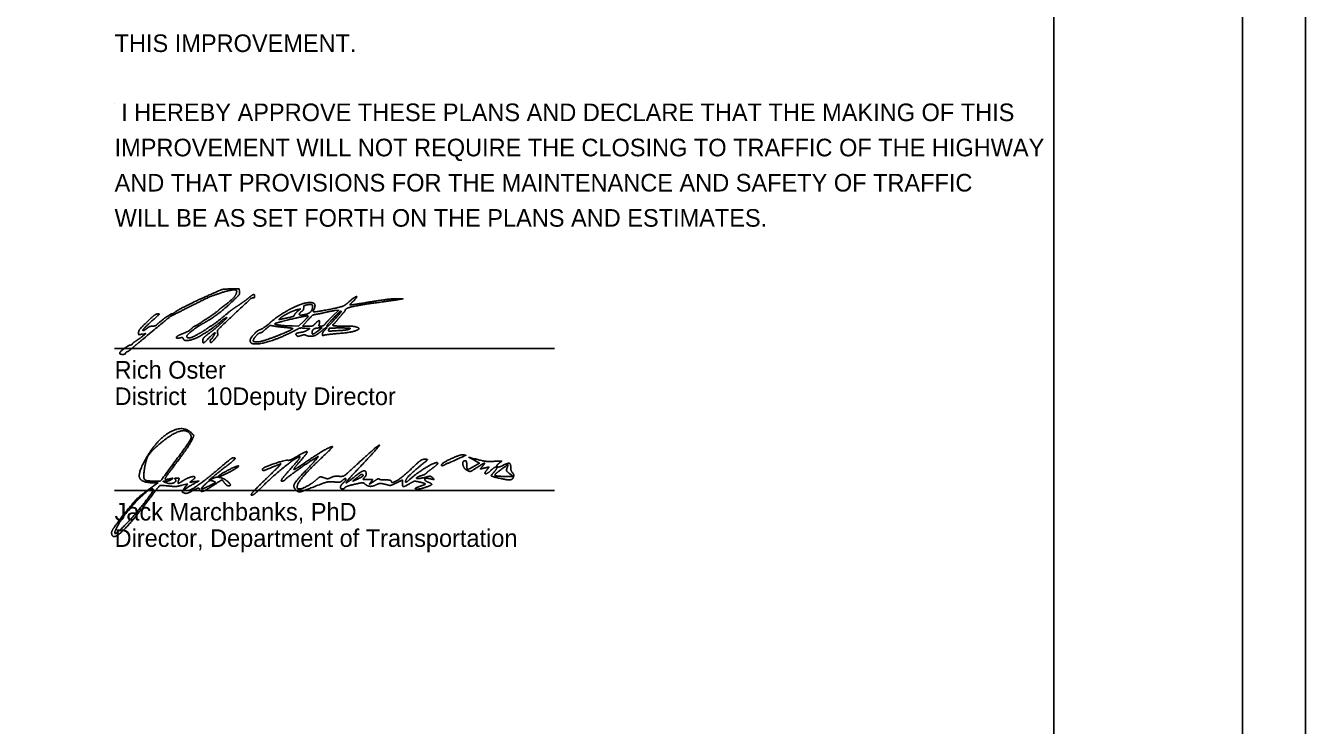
# Model space of a CAD drawing. Extents: x -20.2 to 34, y 0 to 22.
# Drawn here: x 23.82 to 34, y 5.57 to 11.14 of the extents above; entities that cross this region are included whole.
import ezdxf

# ---------------------------------------------------------------- set-up
doc = ezdxf.new("R2010")
doc.units = 0
for name, color, linetype in [('SH_Border', 7, 'Continuous'), ('SH_Cut_Line', 7, 'Continuous'), ('SH_Data', 7, 'Continuous'), ('SH_Text', 7, 'Continuous')]:
    doc.layers.add(name, color=color, linetype=linetype)

msp = doc.modelspace()

# ---------------------------------------------------------------- linework, layer by layer
at = {"layer": 'SH_Border'}
msp.add_line((32, 0.5), (32, 21.5), dxfattribs=at)
msp.add_lwpolyline([(1.5, 21.5), (33.5, 21.5), (33.5, 0.5), (1.5, 0.5)], close=True, dxfattribs=at)
at = {"layer": 'SH_Cut_Line'}
msp.add_lwpolyline([(0, 0), (34, 0), (34, 22), (0, 22)], close=True, dxfattribs=at)
at = {"layer": 'SH_Data'}
for p, q in [((24.528, 10.517), (24.528, 10.517)), ((24.528, 8.568), (28.028, 8.568)), ((24.528, 7.439), (28.028, 7.439))]:
    msp.add_line(p, q, dxfattribs=at)
at = {"layer": 'SH_Text'}
for p, q in [((24.569, 8.531), (24.569, 8.531)), ((24.99, 7.644), (24.99, 7.644)), ((27.129, 7.643), (27.129, 7.643)), ((25.356, 7.554), (25.356, 7.554)), ((26.504, 7.556), (26.504, 7.556)), ((27.582, 7.537), (27.582, 7.537)), ((25.311, 7.513), (25.311, 7.513)), ((25.727, 7.525), (25.727, 7.525))]:
    msp.add_line(p, q, dxfattribs=at)
for points in [[(25.521, 9.021), (25.518, 9.042), (25.458, 9.042)], [(26.782, 8.956), (26.823, 8.962), (26.785, 8.963)], [(25.983, 8.878), (26.006, 8.883), (25.981, 8.861)], [(26.278, 8.869), (26.311, 8.874), (26.267, 8.831)], [(26.032, 8.784), (25.992, 8.746), (25.939, 8.747)], [(26.064, 8.746), (26.023, 8.746), (26.063, 8.791)], [(24.747, 8.682), (24.776, 8.687), (24.753, 8.668)], [(26.041, 8.73), (26.08, 8.727), (26.059, 8.713)], [(26.152, 8.731), (26.177, 8.731), (26.147, 8.709)], [(27.393, 7.634), (27.43, 7.655), (27.389, 7.678)], [(26.453, 7.537), (26.423, 7.511), (26.464, 7.531)], [(27.642, 7.55), (27.698, 7.55), (27.669, 7.572)], [(24.843, 7.477), (24.873, 7.498), (24.835, 7.499)], [(25.085, 7.457), (25.107, 7.49), (25.065, 7.48)]]:
    msp.add_lwpolyline(points, dxfattribs=at)
for points in [[(25.233, 8.972), (25.153, 8.936), (25.017, 8.866), (25.004, 8.854)], [(25.151, 8.913), (25.263, 8.97), (25.288, 8.981), (25.361, 9.006)], [(25.458, 9.042), (25.396, 9.041), (25.369, 9.033), (25.233, 8.972)], [(25.361, 9.006), (25.425, 9.028), (25.499, 9.038), (25.499, 9.024)], [(25.375, 8.742), (25.597, 8.952), (25.619, 8.971), (25.632, 8.971)], [(25.499, 9.024), (25.499, 9), (25.454, 8.949), (25.395, 8.905)], [(25.46, 8.938), (25.514, 8.99), (25.523, 9.002), (25.521, 9.021)], [(25.593, 8.969), (25.576, 8.955), (25.539, 8.929), (25.511, 8.91)], [(25.642, 8.982), (25.642, 9), (25.624, 8.996), (25.593, 8.969)], [(25.632, 8.971), (25.638, 8.971), (25.642, 8.976), (25.642, 8.982)], [(26.429, 8.947), (26.465, 8.984), (26.436, 8.978), (26.393, 8.94)], [(26.785, 8.963), (26.741, 8.964), (26.657, 8.954), (26.525, 8.933)], [(24.742, 8.633), (24.966, 8.819), (24.976, 8.826), (25.151, 8.913)], [(25.355, 8.872), (25.34, 8.857), (25.173, 8.746), (25.166, 8.746)], [(25.237, 8.77), (25.291, 8.799), (25.406, 8.885), (25.46, 8.938)], [(25.395, 8.905), (25.38, 8.894), (25.362, 8.88), (25.355, 8.872)], [(25.511, 8.91), (25.482, 8.891), (25.448, 8.867), (25.436, 8.857)], [(25.94, 8.889), (25.898, 8.869), (25.789, 8.797), (25.763, 8.771)], [(25.844, 8.808), (25.859, 8.823), (25.954, 8.871), (25.983, 8.878)], [(26.084, 8.934), (26.057, 8.934), (25.995, 8.915), (25.94, 8.889)], [(25.981, 8.861), (25.968, 8.849), (25.957, 8.835), (25.957, 8.831)], [(26.086, 8.859), (26.07, 8.842), (25.989, 8.829), (25.998, 8.845)], [(25.998, 8.845), (26.002, 8.85), (26.011, 8.859), (26.018, 8.865)], [(26.018, 8.865), (26.026, 8.87), (26.032, 8.882), (26.032, 8.892)], [(26.032, 8.892), (26.032, 8.905), (26.037, 8.91), (26.055, 8.914)], [(26.055, 8.914), (26.068, 8.917), (26.083, 8.919), (26.089, 8.919)], [(26.114, 8.881), (26.127, 8.905), (26.111, 8.934), (26.084, 8.934)], [(26.089, 8.919), (26.104, 8.919), (26.102, 8.876), (26.086, 8.859)], [(26.11, 8.861), (26.107, 8.863), (26.11, 8.872), (26.114, 8.881)], [(26.343, 8.904), (26.316, 8.894), (26.114, 8.856), (26.11, 8.861)], [(26.204, 8.855), (26.227, 8.86), (26.26, 8.867), (26.278, 8.869)], [(26.329, 8.864), (26.332, 8.861), (26.308, 8.832), (26.256, 8.775)], [(26.304, 8.846), (26.316, 8.858), (26.327, 8.866), (26.329, 8.864)], [(26.309, 8.806), (26.328, 8.829), (26.347, 8.852), (26.352, 8.857)], [(26.393, 8.94), (26.374, 8.923), (26.351, 8.907), (26.343, 8.904)], [(26.352, 8.857), (26.358, 8.863), (26.362, 8.87), (26.362, 8.873)], [(26.362, 8.873), (26.362, 8.888), (26.484, 8.915), (26.655, 8.938)], [(26.525, 8.933), (26.405, 8.913), (26.396, 8.915), (26.429, 8.947)], [(26.655, 8.938), (26.702, 8.945), (26.759, 8.953), (26.782, 8.956)], [(24.783, 8.777), (24.737, 8.732), (24.719, 8.709), (24.719, 8.696)], [(24.752, 8.711), (24.749, 8.714), (24.796, 8.761), (24.852, 8.811)], [(24.862, 8.842), (24.854, 8.841), (24.819, 8.812), (24.783, 8.777)], [(24.867, 8.76), (24.86, 8.752), (24.843, 8.746), (24.831, 8.746)], [(24.852, 8.811), (24.88, 8.835), (24.883, 8.846), (24.862, 8.842)], [(24.985, 8.844), (24.976, 8.844), (24.886, 8.78), (24.867, 8.76)], [(25.004, 8.854), (24.997, 8.848), (24.989, 8.844), (24.985, 8.844)], [(25.102, 8.666), (25.102, 8.676), (25.198, 8.749), (25.237, 8.77)], [(25.155, 8.642), (25.192, 8.655), (25.319, 8.736), (25.364, 8.776)], [(25.436, 8.857), (25.391, 8.818), (25.298, 8.746), (25.293, 8.746)], [(25.38, 8.773), (25.366, 8.76), (25.348, 8.744), (25.341, 8.738)], [(25.364, 8.776), (25.379, 8.789), (25.397, 8.803), (25.405, 8.807)], [(25.405, 8.807), (25.425, 8.819), (25.413, 8.801), (25.38, 8.773)], [(25.763, 8.771), (25.748, 8.756), (25.689, 8.716), (25.681, 8.716)], [(25.802, 8.763), (25.8, 8.765), (25.825, 8.774), (25.857, 8.782)], [(25.939, 8.747), (25.884, 8.748), (25.809, 8.757), (25.802, 8.763)], [(25.852, 8.801), (25.835, 8.797), (25.834, 8.798), (25.844, 8.808)], [(25.914, 8.814), (25.89, 8.809), (25.862, 8.803), (25.852, 8.801)], [(25.857, 8.782), (25.954, 8.807), (26.063, 8.83), (26.067, 8.826)], [(25.957, 8.831), (25.957, 8.827), (25.937, 8.819), (25.914, 8.814)], [(26.067, 8.826), (26.069, 8.824), (26.053, 8.805), (26.032, 8.784)], [(26.063, 8.791), (26.095, 8.827), (26.107, 8.836), (26.132, 8.84)], [(26.123, 8.765), (26.108, 8.749), (26.098, 8.746), (26.064, 8.746)], [(26.156, 8.765), (26.162, 8.79), (26.146, 8.79), (26.123, 8.765)], [(26.132, 8.84), (26.149, 8.843), (26.182, 8.849), (26.204, 8.855)], [(26.17, 8.746), (26.154, 8.746), (26.152, 8.749), (26.156, 8.765)], [(26.206, 8.767), (26.196, 8.754), (26.182, 8.746), (26.17, 8.746)], [(26.267, 8.831), (26.243, 8.807), (26.215, 8.778), (26.206, 8.767)], [(26.22, 8.746), (26.212, 8.746), (26.233, 8.771), (26.304, 8.846)], [(26.256, 8.775), (26.241, 8.759), (26.225, 8.746), (26.22, 8.746)], [(26.264, 8.753), (26.264, 8.757), (26.267, 8.761), (26.27, 8.762)], [(26.27, 8.762), (26.273, 8.764), (26.291, 8.783), (26.309, 8.806)], [(24.753, 8.668), (24.741, 8.658), (24.716, 8.64), (24.699, 8.629)], [(24.719, 8.696), (24.719, 8.678), (24.721, 8.677), (24.747, 8.682)], [(24.782, 8.726), (24.768, 8.715), (24.755, 8.708), (24.752, 8.711)], [(24.831, 8.746), (24.818, 8.746), (24.797, 8.738), (24.782, 8.726)], [(25.051, 8.678), (25.02, 8.665), (25.018, 8.645), (25.048, 8.652)], [(25.048, 8.652), (25.064, 8.656), (25.071, 8.654), (25.074, 8.645)], [(25.141, 8.727), (25.122, 8.71), (25.107, 8.702), (25.051, 8.678)], [(25.18, 8.675), (25.143, 8.654), (25.102, 8.65), (25.102, 8.666)], [(25.166, 8.746), (25.163, 8.746), (25.152, 8.738), (25.141, 8.727)], [(25.28, 8.739), (25.265, 8.726), (25.217, 8.696), (25.18, 8.675)], [(25.287, 8.694), (25.247, 8.665), (25.229, 8.644), (25.229, 8.627)], [(25.279, 8.652), (25.318, 8.691), (25.332, 8.696), (25.313, 8.664)], [(25.293, 8.746), (25.291, 8.746), (25.285, 8.743), (25.28, 8.739)], [(25.341, 8.738), (25.334, 8.731), (25.31, 8.712), (25.287, 8.694)], [(25.313, 8.664), (25.306, 8.651), (25.298, 8.641), (25.295, 8.641)], [(25.327, 8.646), (25.344, 8.666), (25.35, 8.678), (25.347, 8.692)], [(25.347, 8.692), (25.344, 8.708), (25.35, 8.718), (25.375, 8.742)], [(25.681, 8.716), (25.67, 8.716), (25.613, 8.658), (25.608, 8.641)], [(25.635, 8.644), (25.645, 8.662), (25.679, 8.693), (25.691, 8.693)], [(25.652, 8.604), (25.702, 8.604), (25.861, 8.659), (25.959, 8.709)], [(25.691, 8.693), (25.695, 8.694), (25.706, 8.7), (25.713, 8.707)], [(25.713, 8.707), (25.758, 8.747), (25.769, 8.752), (25.797, 8.746)], [(25.944, 8.724), (25.935, 8.716), (25.833, 8.672), (25.769, 8.649)], [(25.797, 8.746), (25.813, 8.743), (25.854, 8.738), (25.888, 8.735)], [(25.888, 8.735), (25.922, 8.732), (25.948, 8.727), (25.944, 8.724)], [(25.959, 8.709), (25.993, 8.728), (26.009, 8.732), (26.041, 8.73)], [(26.008, 8.696), (25.977, 8.691), (25.966, 8.682), (25.978, 8.67)], [(25.978, 8.67), (25.983, 8.664), (25.994, 8.665), (26.012, 8.671)], [(26.059, 8.713), (26.047, 8.706), (26.024, 8.698), (26.008, 8.696)], [(26.012, 8.671), (26.027, 8.676), (26.043, 8.677), (26.048, 8.674)], [(26.048, 8.674), (26.062, 8.666), (26.109, 8.665), (26.126, 8.673)], [(26.099, 8.696), (26.099, 8.714), (26.126, 8.731), (26.152, 8.731)], [(26.147, 8.709), (26.116, 8.685), (26.099, 8.68), (26.099, 8.696)], [(26.126, 8.673), (26.134, 8.677), (26.155, 8.692), (26.173, 8.707)], [(26.173, 8.707), (26.205, 8.733), (26.225, 8.738), (26.197, 8.712)], [(26.197, 8.712), (26.189, 8.705), (26.182, 8.692), (26.182, 8.684)], [(26.182, 8.684), (26.182, 8.672), (26.185, 8.67), (26.199, 8.675)], [(26.199, 8.675), (26.208, 8.677), (26.251, 8.682), (26.294, 8.686)], [(26.305, 8.71), (26.241, 8.706), (26.227, 8.707), (26.23, 8.715)], [(26.23, 8.715), (26.233, 8.72), (26.234, 8.726), (26.234, 8.728)], [(26.234, 8.728), (26.234, 8.73), (26.274, 8.731), (26.322, 8.731)], [(26.345, 8.746), (26.301, 8.746), (26.264, 8.749), (26.264, 8.753)], [(26.294, 8.686), (26.406, 8.694), (26.494, 8.728), (26.443, 8.741)], [(26.397, 8.723), (26.389, 8.718), (26.347, 8.712), (26.305, 8.71)], [(26.322, 8.731), (26.389, 8.731), (26.407, 8.729), (26.397, 8.723)], [(26.443, 8.741), (26.433, 8.744), (26.389, 8.746), (26.345, 8.746)], [(24.659, 8.596), (24.645, 8.596), (24.569, 8.542), (24.569, 8.531)], [(24.627, 8.542), (24.635, 8.544), (24.649, 8.554), (24.659, 8.563)], [(24.659, 8.563), (24.67, 8.573), (24.707, 8.604), (24.742, 8.633)], [(24.667, 8.602), (24.667, 8.599), (24.663, 8.596), (24.659, 8.596)], [(24.699, 8.629), (24.681, 8.617), (24.667, 8.605), (24.667, 8.602)], [(25.074, 8.645), (25.08, 8.631), (25.119, 8.63), (25.155, 8.642)], [(25.229, 8.627), (25.229, 8.61), (25.247, 8.619), (25.279, 8.652)], [(25.289, 8.63), (25.289, 8.612), (25.301, 8.617), (25.327, 8.646)], [(25.295, 8.641), (25.292, 8.641), (25.289, 8.636), (25.289, 8.63)], [(25.608, 8.641), (25.605, 8.632), (25.607, 8.621), (25.612, 8.615)], [(25.612, 8.615), (25.617, 8.608), (25.634, 8.604), (25.652, 8.604)], [(25.636, 8.624), (25.629, 8.626), (25.629, 8.631), (25.635, 8.644)], [(25.769, 8.649), (25.712, 8.628), (25.653, 8.617), (25.636, 8.624)], [(24.569, 8.531), (24.569, 8.525), (24.578, 8.521), (24.592, 8.521)], [(24.592, 8.521), (24.604, 8.521), (24.614, 8.525), (24.614, 8.529)], [(24.614, 8.529), (24.614, 8.533), (24.62, 8.539), (24.627, 8.542)], [(24.779, 7.695), (24.865, 7.845), (25.073, 7.961), (25.139, 7.896)], [(25.13, 7.886), (25.104, 7.928), (24.978, 7.887), (24.883, 7.806)], [(24.99, 7.644), (25.112, 7.808), (25.144, 7.864), (25.13, 7.886)], [(25.139, 7.896), (25.158, 7.877), (25.158, 7.872), (25.139, 7.833)], [(24.883, 7.806), (24.816, 7.749), (24.777, 7.684), (24.766, 7.613)], [(25.139, 7.833), (25.128, 7.81), (25.077, 7.735), (25.024, 7.665)], [(25.974, 7.707), (26.052, 7.753), (26.065, 7.74), (26.005, 7.672)], [(26.033, 7.653), (26.113, 7.71), (26.244, 7.787), (26.26, 7.787)], [(26.26, 7.787), (26.265, 7.787), (26.224, 7.745), (26.168, 7.692)], [(26.487, 7.674), (26.562, 7.743), (26.628, 7.799), (26.634, 7.799)], [(26.634, 7.799), (26.639, 7.8), (26.587, 7.739), (26.518, 7.666)], [(24.835, 7.499), (24.737, 7.501), (24.714, 7.582), (24.779, 7.695)], [(24.844, 7.512), (24.891, 7.512), (24.895, 7.516), (24.99, 7.644)], [(25.024, 7.665), (24.972, 7.596), (24.929, 7.535), (24.929, 7.531)], [(25.369, 7.621), (25.419, 7.664), (25.465, 7.699), (25.47, 7.699)], [(25.47, 7.699), (25.495, 7.7), (25.472, 7.674), (25.386, 7.607)], [(26.002, 7.707), (25.992, 7.716), (25.782, 7.549), (25.704, 7.47)], [(25.705, 7.609), (25.705, 7.62), (25.892, 7.683), (25.908, 7.678)], [(25.727, 7.525), (25.798, 7.594), (25.854, 7.65), (25.85, 7.65)], [(25.85, 7.65), (25.847, 7.65), (25.818, 7.638), (25.786, 7.625)], [(26.142, 7.706), (26.093, 7.678), (25.905, 7.546), (25.891, 7.53)], [(25.908, 7.678), (25.914, 7.676), (25.943, 7.689), (25.974, 7.707)], [(25.924, 7.606), (25.97, 7.658), (26.005, 7.703), (26.002, 7.707)], [(26.005, 7.672), (25.977, 7.641), (25.954, 7.611), (25.954, 7.606)], [(25.954, 7.606), (25.954, 7.602), (25.99, 7.623), (26.033, 7.653)], [(26.168, 7.692), (26.069, 7.599), (25.979, 7.491), (25.979, 7.464)], [(26.077, 7.627), (26.123, 7.676), (26.152, 7.712), (26.142, 7.706)], [(26.312, 7.551), (26.345, 7.548), (26.369, 7.565), (26.487, 7.674)], [(26.518, 7.666), (26.388, 7.528), (26.356, 7.481), (26.439, 7.549)], [(26.967, 7.64), (26.893, 7.579), (26.842, 7.525), (26.842, 7.508)], [(26.876, 7.526), (26.93, 7.575), (27.077, 7.665), (27.094, 7.659)], [(26.895, 7.617), (26.94, 7.661), (26.977, 7.687), (26.995, 7.687)], [(26.995, 7.687), (27.019, 7.686), (27.016, 7.68), (26.967, 7.64)], [(27.094, 7.659), (27.102, 7.657), (27.087, 7.638), (27.06, 7.618)], [(27.129, 7.643), (27.129, 7.656), (27.282, 7.726), (27.301, 7.722)], [(27.201, 7.664), (27.138, 7.636), (27.129, 7.633), (27.129, 7.643)], [(27.301, 7.722), (27.322, 7.718), (27.323, 7.719), (27.201, 7.664)], [(27.33, 7.599), (27.304, 7.613), (27.293, 7.675), (27.317, 7.675)], [(27.317, 7.675), (27.324, 7.675), (27.329, 7.661), (27.329, 7.643)], [(27.329, 7.643), (27.329, 7.607), (27.344, 7.604), (27.393, 7.634)], [(27.389, 7.678), (27.346, 7.702), (27.345, 7.702), (27.448, 7.676)], [(27.453, 7.629), (27.477, 7.658), (27.461, 7.655), (27.405, 7.617)], [(27.448, 7.676), (27.469, 7.671), (27.514, 7.668), (27.548, 7.67)], [(27.548, 7.67), (27.603, 7.673), (27.608, 7.671), (27.588, 7.656)], [(27.588, 7.656), (27.559, 7.635), (27.582, 7.619), (27.616, 7.637)], [(27.65, 7.618), (27.66, 7.644), (27.651, 7.641), (27.589, 7.595)], [(27.616, 7.637), (27.656, 7.658), (27.679, 7.652), (27.679, 7.621)], [(24.766, 7.613), (24.755, 7.54), (24.776, 7.512), (24.844, 7.512)], [(24.964, 7.53), (24.989, 7.536), (24.993, 7.535), (24.979, 7.525)], [(25.009, 7.529), (25.004, 7.533), (25.01, 7.537), (25.022, 7.537)], [(25.022, 7.537), (25.037, 7.537), (25.042, 7.531), (25.037, 7.518)], [(25.074, 7.517), (25.102, 7.536), (25.167, 7.554), (25.167, 7.542)], [(25.108, 7.437), (25.131, 7.437), (25.257, 7.526), (25.369, 7.621)], [(25.167, 7.542), (25.167, 7.537), (25.157, 7.527), (25.145, 7.518)], [(25.386, 7.607), (25.293, 7.534), (25.271, 7.513), (25.315, 7.536)], [(25.315, 7.536), (25.328, 7.543), (25.351, 7.545), (25.368, 7.541)], [(25.359, 7.55), (25.354, 7.55), (25.353, 7.552), (25.356, 7.554)], [(25.356, 7.554), (25.376, 7.572), (25.508, 7.638), (25.513, 7.633)], [(25.513, 7.633), (25.519, 7.626), (25.377, 7.55), (25.359, 7.55)], [(25.368, 7.541), (25.404, 7.532), (25.463, 7.475), (25.436, 7.475)], [(25.786, 7.625), (25.723, 7.598), (25.704, 7.594), (25.705, 7.609)], [(25.858, 7.512), (25.848, 7.512), (25.877, 7.553), (25.924, 7.606)], [(25.97, 7.442), (25.945, 7.467), (25.973, 7.517), (26.077, 7.627)], [(26.137, 7.527), (26.157, 7.545), (26.17, 7.548), (26.194, 7.539)], [(26.194, 7.539), (26.214, 7.531), (26.233, 7.532), (26.249, 7.541)], [(26.249, 7.541), (26.262, 7.548), (26.291, 7.553), (26.312, 7.551)], [(26.367, 7.528), (26.367, 7.535), (26.357, 7.532), (26.344, 7.521)], [(26.439, 7.549), (26.487, 7.589), (26.529, 7.599), (26.529, 7.571)], [(26.504, 7.556), (26.504, 7.57), (26.48, 7.561), (26.453, 7.537)], [(26.464, 7.531), (26.486, 7.541), (26.504, 7.553), (26.504, 7.556)], [(26.514, 7.54), (26.503, 7.528), (26.509, 7.525), (26.541, 7.525)], [(26.529, 7.571), (26.529, 7.562), (26.523, 7.548), (26.514, 7.54)], [(26.729, 7.511), (26.729, 7.488), (26.825, 7.549), (26.895, 7.617)], [(26.97, 7.557), (26.921, 7.541), (26.94, 7.528), (26.992, 7.541)], [(27.004, 7.573), (27.001, 7.569), (26.986, 7.562), (26.97, 7.557)], [(26.992, 7.541), (27.03, 7.552), (27.045, 7.551), (27.058, 7.539)], [(27.039, 7.531), (27.002, 7.54), (26.989, 7.517), (27.023, 7.504)], [(27.06, 7.618), (27.033, 7.598), (27.008, 7.578), (27.004, 7.573)], [(27.058, 7.539), (27.07, 7.526), (27.067, 7.524), (27.039, 7.531)], [(27.405, 7.617), (27.365, 7.591), (27.352, 7.588), (27.33, 7.599)], [(27.472, 7.617), (27.439, 7.609), (27.437, 7.61), (27.453, 7.629)], [(27.492, 7.606), (27.507, 7.624), (27.505, 7.625), (27.472, 7.617)], [(27.521, 7.598), (27.489, 7.568), (27.466, 7.575), (27.492, 7.606)], [(27.546, 7.585), (27.577, 7.619), (27.555, 7.63), (27.521, 7.598)], [(27.582, 7.537), (27.527, 7.55), (27.522, 7.558), (27.546, 7.585)], [(27.589, 7.595), (27.546, 7.564), (27.563, 7.55), (27.642, 7.55)], [(27.7, 7.544), (27.692, 7.523), (27.651, 7.521), (27.582, 7.537)], [(27.669, 7.572), (27.649, 7.588), (27.643, 7.601), (27.65, 7.618)], [(27.679, 7.621), (27.679, 7.605), (27.686, 7.586), (27.694, 7.578)], [(27.694, 7.578), (27.701, 7.57), (27.704, 7.555), (27.7, 7.544)], [(24.835, 7.448), (24.814, 7.469), (24.596, 7.243), (24.55, 7.153)], [(24.592, 7.235), (24.669, 7.335), (24.749, 7.413), (24.843, 7.477)], [(24.62, 7.172), (24.687, 7.241), (24.843, 7.44), (24.835, 7.448)], [(24.924, 7.477), (24.89, 7.481), (24.879, 7.47), (24.802, 7.368)], [(24.936, 7.512), (24.913, 7.511), (24.914, 7.509), (24.94, 7.499)], [(25.065, 7.48), (25.025, 7.47), (25.002, 7.469), (24.924, 7.477)], [(24.929, 7.531), (24.929, 7.526), (24.945, 7.526), (24.964, 7.53)], [(24.979, 7.525), (24.969, 7.518), (24.949, 7.512), (24.936, 7.512)], [(24.94, 7.499), (24.97, 7.487), (25.026, 7.511), (25.009, 7.529)], [(25.037, 7.518), (25.029, 7.495), (25.041, 7.494), (25.074, 7.517)], [(25.084, 7.417), (25.066, 7.424), (25.066, 7.428), (25.085, 7.457)], [(25.151, 7.437), (25.125, 7.422), (25.095, 7.413), (25.084, 7.417)], [(25.152, 7.488), (25.101, 7.46), (25.081, 7.437), (25.108, 7.437)], [(25.145, 7.518), (25.126, 7.504), (25.128, 7.503), (25.161, 7.508)], [(25.202, 7.451), (25.199, 7.459), (25.18, 7.454), (25.151, 7.437)], [(25.161, 7.508), (25.198, 7.513), (25.198, 7.513), (25.152, 7.488)], [(25.316, 7.481), (25.248, 7.436), (25.21, 7.426), (25.202, 7.451)], [(25.258, 7.496), (25.213, 7.456), (25.225, 7.447), (25.283, 7.476)], [(25.311, 7.513), (25.293, 7.519), (25.277, 7.514), (25.258, 7.496)], [(25.283, 7.476), (25.329, 7.5), (25.333, 7.505), (25.311, 7.513)], [(25.401, 7.499), (25.384, 7.523), (25.382, 7.523), (25.316, 7.481)], [(25.436, 7.475), (25.426, 7.475), (25.411, 7.486), (25.401, 7.499)], [(25.617, 7.4), (25.607, 7.401), (25.656, 7.457), (25.727, 7.525)], [(25.704, 7.47), (25.667, 7.431), (25.627, 7.4), (25.617, 7.4)], [(25.891, 7.53), (25.883, 7.52), (25.868, 7.512), (25.858, 7.512)], [(26.169, 7.489), (26.023, 7.431), (25.988, 7.423), (25.97, 7.442)], [(25.979, 7.464), (25.979, 7.456), (25.988, 7.45), (25.998, 7.45)], [(25.998, 7.45), (26.019, 7.45), (26.101, 7.495), (26.137, 7.527)], [(26.275, 7.506), (26.246, 7.51), (26.206, 7.503), (26.169, 7.489)], [(26.344, 7.521), (26.329, 7.506), (26.307, 7.502), (26.275, 7.506)], [(26.341, 7.45), (26.323, 7.45), (26.327, 7.482), (26.348, 7.5)], [(26.359, 7.46), (26.356, 7.454), (26.348, 7.45), (26.341, 7.45)], [(26.348, 7.5), (26.359, 7.508), (26.367, 7.521), (26.367, 7.528)], [(26.436, 7.487), (26.397, 7.478), (26.363, 7.466), (26.359, 7.46)], [(26.52, 7.489), (26.509, 7.5), (26.489, 7.5), (26.436, 7.487)], [(26.616, 7.487), (26.585, 7.47), (26.538, 7.472), (26.52, 7.489)], [(26.541, 7.525), (26.579, 7.525), (26.581, 7.523), (26.565, 7.503)], [(26.565, 7.503), (26.553, 7.488), (26.56, 7.49), (26.587, 7.509)], [(26.587, 7.509), (26.609, 7.524), (26.629, 7.533), (26.633, 7.529)], [(26.681, 7.487), (26.654, 7.494), (26.631, 7.494), (26.616, 7.487)], [(26.633, 7.529), (26.637, 7.525), (26.66, 7.522), (26.685, 7.522)], [(26.77, 7.498), (26.732, 7.48), (26.714, 7.477), (26.681, 7.487)], [(26.685, 7.522), (26.709, 7.522), (26.729, 7.517), (26.729, 7.511)], [(26.817, 7.498), (26.817, 7.521), (26.816, 7.521), (26.77, 7.498)], [(26.879, 7.495), (26.834, 7.468), (26.817, 7.469), (26.817, 7.498)], [(26.842, 7.508), (26.842, 7.501), (26.857, 7.509), (26.876, 7.526)], [(26.962, 7.503), (26.923, 7.513), (26.906, 7.511), (26.879, 7.495)], [(26.998, 7.462), (26.952, 7.447), (26.904, 7.452), (26.948, 7.468)], [(26.948, 7.468), (26.962, 7.473), (26.982, 7.48), (26.992, 7.484)], [(26.992, 7.484), (27.003, 7.488), (26.992, 7.496), (26.962, 7.503)], [(27.023, 7.504), (27.054, 7.492), (27.045, 7.478), (26.998, 7.462)], [(24.802, 7.368), (24.65, 7.166), (24.504, 7.038), (24.504, 7.105)], [(24.504, 7.105), (24.504, 7.114), (24.544, 7.173), (24.592, 7.235)], [(24.55, 7.153), (24.518, 7.092), (24.55, 7.1), (24.62, 7.172)]]:
    msp.add_open_spline(points, degree=2, dxfattribs=at)

# ---------------------------------------------------------------- texts
at = {"layer": 'SH_Data'}
for s, p in [(' I HEREBY APPROVE THESE PLANS AND DECLARE THAT THE MAKING OF THIS', (24.528, 10.377)), ('IMPROVEMENT WILL NOT REQUIRE THE CLOSING TO TRAFFIC OF THE HIGHWAY', (24.528, 10.097)), ('AND THAT PROVISIONS FOR THE MAINTENANCE AND SAFETY OF TRAFFIC', (24.528, 9.817)), ('WILL BE AS SET FORTH ON THE PLANS AND ESTIMATES.', (24.528, 9.537))]:
    msp.add_text(s, height=0.14, dxfattribs=at).set_placement(p)
at = {"layer": 'SH_Text'}
for s, p in [('THIS IMPROVEMENT.', (24.528, 10.927)), ('Rich Oster', (24.528, 8.328)), ('District       Deputy Director', (24.528, 8.118)), ('              10', (24.528, 8.118)), ('Jack Marchbanks, PhD', (24.528, 7.199)), ('Director, Department of Transportation', (24.528, 6.989))]:
    msp.add_text(s, height=0.14, dxfattribs=at).set_placement(p)

doc.saveas('drawing.dxf')
